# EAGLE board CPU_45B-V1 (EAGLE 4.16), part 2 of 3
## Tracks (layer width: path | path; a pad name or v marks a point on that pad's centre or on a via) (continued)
P1.7  (via drill 0.2) (continued)
  Top 0.12: U300.B10 52.15,41.23 52.15,40.59 52.23,40.51 52.23,38.43 | U430.C2 38.15,43.23 v41.91,43.23 | 52.23,38.43 52.55,38.11 52.55,36.91 52.23,36.59 49.27,36.59 v48.87,36.99 | v44.95,35.07 44.63,34.75 23.71,34.75 14.51,43.95 9.31,43.95 7.07,46.19 5.19,46.19 3.75,45.79 X200.70 | 52.23,38.43
  Route3 0.12: v48.87,36.99 48.31,37.55 | v41.91,43.23 41.91,42.95 47.31,37.55 48.31,37.55 | 48.31,37.55
  Route14 0.12: v44.95,35.07 47.43,37.55 48.31,37.55 v48.87,36.99
P1.8  (via drill 0.2)
  Top 0.12: U430.C1 41.19,43.63 41.43,43.87 v41.67,43.87 | v48.39,38.11 48.39,36.83 48.87,36.35 52.35,36.35 52.83,36.83 52.83,38.35 52.55,38.63 U300.A10 | v44.15,35.15 43.99,34.99 23.83,34.99 14.63,44.19 9.43,44.19 6.71,46.91 4.95,46.91 3.59,46.59 X200.72
  Route3 0.12: 42.07,43.87 | 42.07,43.87 v41.67,43.87 | v48.39,38.11 47.11,38.11 42.51,42.71 42.51,43.43 42.07,43.87 | 42.07,43.87 v41.67,43.87 | v41.67,43.87
  Route14 0.12: v48.39,38.11 47.11,38.11 v44.15,35.15
P1.9  (via drill 0.2)
  Top 0.12: U300.B11 51.35,41.23 51.35,40.59 51.27,40.51 51.27,39.71 51.07,39.51 v51.07,38.59 | U430.B2 37.35,42.43 v37.35,41.23 | v44.23,35.87 43.59,35.23 23.95,35.23 14.75,44.43 9.55,44.43 6.27,47.71 4.71,47.71 3.35,47.31 X200.74
  Route3 0.12: v37.35,41.23 39.07,41.23 44.23,36.07 v44.23,35.87
  Route14 0.12: v51.07,38.59 51.03,38.59 46.95,38.59 v44.23,35.87
P1.10  (via drill 0.2)
  Top 0.12: 50.15,43.23 U300.D12 | 50.15,43.23 | 50.15,43.23 49.91,43.23 v49.43,42.75
  Route3 0.12: v12.79,24.11 13.19,23.71 13.91,23.71 14.79,24.59 22.87,24.59 23.35,25.07 50.23,25.07 v50.71,25.55
  Route14 0.12: v49.43,42.75 49.43,41.63 51.99,39.07 51.99,37.87 50.47,36.35 50.47,25.79 v50.71,25.55
  Bottom 0.12: X200.19 11.19,23.63 12.31,23.63 v12.79,24.11
P1.11  (via drill 0.2)
  Top 0.12: U300.D11 51.35,43.63 49.59,43.63 v48.71,42.75
  Route3 0.12: v13.59,24.11 14.31,24.83 22.71,24.83 23.19,25.31 49.03,25.31 49.27,25.55 v49.99,25.55
  Route14 0.12: v48.71,42.75 48.71,41.99 51.75,38.95 51.75,38.03 50.23,36.51 50.23,25.79 v49.99,25.55
  Bottom 0.12: X200.17 11.35,22.99 11.67,23.31 12.79,23.31 v13.59,24.11
P1.12  (via drill 0.2)
  Top 0.12: v34.15,48.03 U430.H7 | U300.E11 51.35,44.43 v49.59,44.43
  Route3 0.12: v49.59,44.43 42.87,44.43 40.95,46.35 37.95,46.35 37.39,45.79 36.19,45.79 34.87,47.11 34.87,47.71 34.55,48.03 | v34.15,48.03 34.55,48.03 | 34.55,48.03
P1.13  (via drill 0.2)
  Top 0.12: v32.55,48.03 U430.H8 | v49.11,44.03 U300.E12 | v49.11,44.03
  Route3 0.12: v49.11,44.03 42.87,44.03 40.79,46.11 38.07,46.11 37.51,45.55 34.31,45.55 33.35,46.51 33.35,47.23 v32.55,48.03
P1.14  (via drill 0.2)
  Top 0.12: v32.55,48.83 U430.J8
  Top 0.127: v52.15,43.63 U300.E10
  Route3 0.12: v52.15,43.63 42.87,43.63 40.63,45.87 38.19,45.87 37.63,45.31 32.95,45.31 32.15,46.11 32.15,48.43 v32.55,48.83 | v32.55,48.83
P1.15  (via drill 0.2)
  Top 0.12: U430.J7 v34.15,48.83 | U300.G12 v49.11,45.63
  Route3 0.12: v49.11,45.63 48.71,45.23 42.47,45.23 41.11,46.59 37.83,46.59 37.27,46.03 36.31,46.03 35.11,47.23 35.11,47.87 v34.15,48.83
P2.0  (via drill 0.2)
  Top 0.12: v36.55,48.83 U430.J3 | U300.J11 51.35,47.63 49.59,47.63 v49.11,47.15
  Route3 0.12: v49.11,47.15 48.55,47.15 48.23,46.83 36.31,46.83 36.15,46.99 36.15,48.43 v36.55,48.83 | v36.55,48.83
P2.1  (via drill 0.2)
  Top 0.12: U430.J2 38.23,48.91 40.07,48.91 v40.95,48.03 | v40.95,48.03 | v50.39,48.03 U300.K12 | U500.2 36.51,70.46 36.3,70.46 v35.98,70.77 | R404.2 34.79,28.19 35.43,28.19 v37.67,30.43 | U500.24 46.45,70.19 v46.95,70.19
  Route3 0.12: v40.95,48.03 | v40.95,48.03 v50.39,48.03 | v35.98,70.77 40.29,70.77 43.11,67.95 45.91,67.95 46.95,68.99 v46.95,70.19
  Route14 0.12: v37.67,30.43 38.71,31.47 38.71,43.79 40.95,46.03 v40.95,48.03 41.11,48.19 41.11,60.75 43.75,63.39 43.75,63.95 44.63,64.83 46.07,64.83 47.19,65.95 47.19,69.95 v46.95,70.19
P2.2  (via drill 0.2)
  Top 0.12: U430.H3 v36.55,48.03 | U300.K11 51.35,48.43 50.15,48.43 49.75,48.03 49.19,48.03 v48.79,47.63
  Route3 0.12: v36.55,48.03 | v48.79,47.63 U430.H3 v36.55,48.03
P2.3  (via drill 0.2)
  Top 0.12: U430.H2 v38.15,48.03 | 51.35,49.23 U300.L11 | v49.03,48.99 49.35,49.31 50.23,49.31 50.31,49.23 51.35,49.23 | 51.35,49.23
  Route3 0.12: v38.15,48.03 38.79,48.67 48.71,48.67 v49.03,48.99
P2.4  (via drill 0.2)
  Top 0.12: U430.H1 v38.95,48.03 | U300.L10 52.15,49.23 52.15,52.19 48.95,55.39 39.43,55.39 v38.95,54.91
  Route14 0.12: v38.95,48.03 v38.95,54.91
P2.5  (via drill 0.2)
  Top 0.12: U430.G3 v36.55,47.23 | U300.M10 52.55,52.15 49.07,55.63 39.03,55.63 38.31,54.91 37.59,54.19 v36.95,54.19
  Route14 0.12: v36.95,54.19 36.95,47.63 v36.55,47.23
P2.6  (via drill 0.2)
  Top 0.12: v11.99,28.27 11.03,28.27 10.47,27.71 8.71,27.23 X200.30
  Top 0.127: v52.95,47.63 U300.J9
  Route3 0.12: v52.95,47.63 52.55,48.03 52.55,48.67 50.39,50.83 33.11,50.83 31.11,48.83 v31.11,47.63 | v11.99,28.27 12.71,27.55 v31.11,27.55
  Route14 0.12: v31.11,27.55 v31.11,47.63
P2.7  (via drill 0.2)
  Top 0.12: v12.07,27.31 10.79,27.31 10.39,26.91 8.87,26.43 X200.28
  Top 0.127: v52.95,48.43 U300.K9
  Route3 0.12: v52.95,48.43 52.95,48.67 50.55,51.07 32.99,51.07 30.63,48.71 v30.63,48.03 | v30.63,27.15 24.95,27.15 24.79,27.31 v12.07,27.31
  Route14 0.12: v30.63,48.03 30.63,47.47 30.87,47.23 30.87,29.15 30.63,28.91 v30.63,27.15
P2.8  (via drill 0.2)
  Top 0.12: U430.H9 v31.75,48.03 | U300.L9 52.95,49.23 52.95,52.11 49.19,55.87 38.87,55.87 37.83,54.83 34.71,54.83 33.51,56.03 v32.15,56.03 | v32.15,56.03 | v32.15,56.03
  Route14 0.12: v31.75,48.03 32.15,48.43 v32.15,56.03
P2.9  (via drill 0.2)
  Top 0.12: U430.G2 v38.15,47.23 | U300.M9 53.35,52.07 49.31,56.11 38.79,56.11 38.47,56.11 v37.75,55.39 | v37.75,55.39 | v37.75,55.39
  Route14 0.12: v38.15,47.23 | v37.75,55.39 37.75,47.63 v38.15,47.23
P2.10  (via drill 0.2)
  Top 0.12: U430.G7 v34.15,47.23 | U300.L8 53.75,49.23 53.75,52.03 49.43,56.35 37.99,56.35 36.71,55.07 35.11,55.07 v34.15,56.03 | v34.15,56.03 | v34.15,56.03
  Route14 0.12: v34.15,47.23 33.75,47.63 33.75,55.63 v34.15,56.03
P2.11  (via drill 0.2)
  Top 0.12: U430.G8 v32.55,47.23 | U300.M8 54.15,51.99 49.55,56.59 37.87,56.59 36.59,55.31 35.91,55.31 34.71,56.51 v32.95,56.51
  Route14 0.12: v32.55,47.23 32.95,47.63 v32.95,56.51
P2.12  (via drill 0.2)
  Top 0.12: U300.L7 54.55,49.23 54.55,53.31 v53.91,53.95 | X200.16 11.51,22.35 v12.71,22.35
  Route3 0.12: v53.91,53.95 50.87,53.95 49.19,52.27 32.31,52.27 29.27,49.23 29.27,47.15 30.31,46.11 30.31,44.63 29.59,43.91 29.59,39.63 | v29.11,38.91 29.11,39.15 29.59,39.63 | 29.59,39.63
  Route14 0.12: v29.11,38.91 29.11,33.23 19.67,23.79 16.75,23.79 15.07,22.11 13.75,22.11 13.59,21.95 13.11,21.95 v12.71,22.35
P2.13  (via drill 0.2)
  Top 0.12: U300.M7 54.95,53.55 54.15,54.35 v53.43,54.35 | X200.14 11.83,21.55 12.55,21.55 v13.35,22.35
  Route3 0.12: v53.43,54.35 53.27,54.19 50.71,54.19 49.03,52.51 32.19,52.51 29.03,49.35 29.03,47.03 30.07,45.99 30.07,44.75 29.35,44.03 29.35,39.79 28.71,39.15 v28.71,38.43
  Route14 0.12: v28.71,38.43 28.71,33.19 19.55,24.03 16.63,24.03 14.95,22.35 v13.35,22.35
P2.14  (via drill 0.2)
  Top 0.12: v32.55,44.83 U430.E8
  Top 0.127: v54.55,48.43 U300.K7
  Route3 0.12: v54.55,48.43 54.15,48.03 53.51,48.03 53.35,48.19 53.35,48.67 50.71,51.31 32.79,51.31 30.23,48.75 30.23,47.63 31.27,46.59 31.27,46.11 v32.55,44.83 | v32.55,44.83 | v32.55,44.83 | v32.55,44.83
  Bottom 0.12: X200.55 6.63,40.75 7.75,40.75 10.55,43.55 28.87,43.55 30.63,45.31 32.07,45.31 v32.55,44.83 | v32.55,44.83 | v32.55,44.83
P2.15  (via drill 0.2)
  Top 0.12: U430.F1 41.67,46.03 v42.31,46.03 | v42.31,46.03
  Top 0.127: v56.15,47.63 U300.J6
  Route3 0.12: v56.15,47.63 | v42.31,46.03 | v42.31,46.03 42.71,46.43 54.95,46.43 v56.15,47.63
  Bottom 0.12: v42.31,46.03 | v42.31,46.03 35.27,46.03 33.67,44.43 30.15,44.43 29.03,43.31 10.71,43.31 7.43,40.03 6.79,40.03 X200.53
P3.0  (via drill 0.2)
  Top 0.12: U300.C1 60.15,42.43 63.35,39.23 v63.83,39.23
  Bottom 0.12: 63.75,39.15 v63.83,39.23 63.51,38.91 55.83,38.91 55.51,39.23 51.07,39.23 47.47,42.83 10.63,42.83 7.03,39.23 X200.51
P3.1  (via drill 0.2)
  Top 0.12: v31.75,46.43 U430.F9 | U300.B2 59.35,41.23 59.99,41.23 60.23,40.99 60.23,39.71 61.03,38.91 61.03,38.03 60.47,37.47 v58.47,37.47 | v31.51,42.43 31.35,42.27 31.35,37.55 31.51,37.39 v31.67,37.39
  Route14 0.12: v31.75,46.43 31.35,46.03 31.35,42.59 v31.51,42.43
  Bottom 0.12: v58.47,37.47 58.31,37.63 42.79,37.63 42.55,37.87 41.99,37.87 41.51,37.39 v31.67,37.39 | X200.49 5.83,38.03 7.27,38.59 7.59,39.39 10.63,42.43 v31.51,42.43
P3.2  (via drill 0.2)
  Top 0.12: v31.75,47.23 U430.G9 | U300.B3 58.55,41.23 58.55,40.27 57.91,39.63 57.91,37.39 v58.47,36.83 | v31.75,47.23 | v28.31,37.07 27.35,38.03 27.35,38.83 29.75,41.23 31.03,42.51 31.03,46.11 31.03,46.51 | v31.75,47.23 | v31.75,47.23 | v31.75,47.23 31.51,46.99 31.03,46.51 | 31.03,46.51 | R431.1 30.58,46.96 31.03,46.51
  Bottom 0.12: v28.31,37.07 28.39,36.99 42.39,36.99 42.79,37.39 57.91,37.39 v58.47,36.83
P3.3  (via drill 0.2)
  Top 0.12: U302.1 24.87,25.87 24.23,26.51 v24.23,26.91 | U302.1 26.07,25.47 | U302.1 25.83,25.55 R309.1 27.67,25.07 SJ1.1
  Top 0.127: v54.55,44.43 U300.F7
  Route3 0.12: v54.95,28.03 54.71,28.27 32.55,28.27 31.03,26.75 24.79,26.75 24.63,26.91 v24.23,26.91
  Route14 0.12: v54.55,44.43 54.95,44.03 v54.95,28.03
P3.4  (via drill 0.2)
  Top 0.12: v54.55,43.63 U300.E7 | v54.55,43.63
  Route3 0.12: v54.55,43.63 54.79,43.63 55.35,43.07 55.35,39.15 55.03,38.83 55.03,30.27 v54.55,29.79 | v60.87,29.79 61.19,29.47 63.99,29.47 64.31,29.79 68.71,29.79 69.03,30.11 70.79,30.11 70.95,30.27 72.07,30.27 72.39,29.95 v72.39,29.63
  Bottom 0.12: v54.55,29.79 54.71,29.63 59.99,29.63 60.15,29.79 v60.87,29.79 | v72.39,29.63 72.39,28.67 77.51,23.55 78.55,23.55 79.75,22.35 | X202.25 81.11,20.03 79.75,21.39 79.75,21.87 79.75,22.35 | 79.75,22.35
P3.5  (via drill 0.2)
  Top 0.12: v33.35,43.23 U430.C8 | U300.B6 56.15,41.23 56.15,40.43 56.31,40.27 56.31,37.75 56.15,37.59 | 56.15,37.59 52.27,33.71 v49.27,33.71 | v49.27,33.71 | v49.27,33.71 48.19,33.71 47.55,33.07 22.87,33.07 13.67,42.27 8.79,42.27 7.59,41.07 5.19,40.35 X200.56 | 56.15,37.59
  Route3 0.12: 39.03,43.23 v33.35,43.23 | v49.27,33.71 | v49.27,33.71 48.55,33.71 39.03,43.23 | 39.03,43.23
P3.6  (via drill 0.2)
  Top 0.12: v32.55,44.03 U430.D9 | 54.95,37.31 U300.A7 | v48.79,34.11 52.31,34.11 54.95,36.75 54.95,37.31 | 54.95,37.31 | 54.95,37.31 | v48.79,34.11 | v48.79,34.11 48.23,34.11 47.43,33.31 22.99,33.31 13.79,42.51 7.43,42.51 6.47,41.55 X200.58
  Route3 0.12: v32.55,44.03 32.95,43.63 39.07,43.63 | v48.79,34.11 | v48.79,34.11 48.59,34.11 39.07,43.63 | 39.07,43.63
P3.7  (via drill 0.2, 0.2 pad 0.55)
  Top 0.12: v76.23,22.91 76.23,21.79 77.51,20.51 77.51,19.07 78.87,17.71 X202.34 | X201.34 53.11,84.43 52.39,81.47 51.35,80.43 v51.35,80.11
  Top 0.127: v57.75,43.63 U300.E4
  Route3 0.12: v57.75,43.63 58.15,43.23 v74.07,43.23 | v51.67,68.43 51.83,68.27 57.91,68.27 58.47,68.83 70.39,68.83 v70.71,69.15
  Route14 0.12: v70.71,69.15 70.71,68.67 73.83,65.55 73.83,45.71 74.07,45.47 v74.07,43.23 75.03,42.27 75.03,35.55 77.11,33.47 77.11,23.79 v76.23,22.91
  Bottom 0.12: v51.67,68.43 51.43,68.67 51.43,71.63 51.19,71.87 51.19,79.55 51.35,79.71 v51.35,80.11
P3.8  (via drill 0.2, 0.2 pad 0.55)
  Top 0.12: v76.87,22.27 76.87,21.55 77.83,20.59 77.83,19.87 79.35,18.35 79.35,18.33 X202.32 | v50.47,79.95 51.99,81.47 51.99,83.23 52.39,84.59 X201.32
  Top 0.127: v58.55,43.63 U300.E3
  Route3 0.12: v58.55,43.63 73.59,43.63 74.87,44.91 v75.03,44.91 | v51.11,68.19 51.27,68.03 58.07,68.03 58.63,68.59 70.87,68.59 71.27,68.99 v71.27,69.55
  Route14 0.12: v71.27,69.55 71.27,68.51 74.07,65.71 74.07,45.87 v75.03,44.91 75.27,44.67 75.27,35.71 77.35,33.63 77.35,22.75 v76.87,22.27
  Bottom 0.12: v51.11,68.19 51.11,70.19 50.47,70.83 v50.47,79.95
P3.9  (via drill 0.2, 0.2 pad 0.55)
  Top 0.12: v75.59,23.55 75.59,22.03 77.19,20.43 77.19,18.27 78.31,17.15 78.27,17.23 X202.36 | X201.36 53.91,84.19 53.27,81.95 51.91,80.59 v51.91,79.15
  Top 0.127: v56.95,44.43 U300.F5
  Route3 0.12: v56.95,44.43 57.35,44.83 v73.19,44.83 | 69.19,69.31 53.11,69.31 v52.71,68.91 | 69.19,69.31 | v69.43,69.55 69.19,69.31
  Route14 0.12: 73.59,65.39 73.59,45.23 v73.19,44.83 73.59,44.43 73.59,42.99 74.79,41.79 74.79,35.39 76.87,33.31 76.87,24.83 v75.59,23.55 | 73.59,65.39 | 73.59,65.39 v69.43,69.55
  Bottom 0.12: v51.91,79.15 51.91,71.95 52.39,71.47 52.39,69.23 v52.71,68.91
P3.10  (via drill 0.2)
  Top 0.12: v54.07,68.75 | v54.07,68.75 | SJ3.1 53.27,69.56 v54.07,68.75 | SJ4.1 77.83,25.16 v77.83,25.31
  Top 0.127: v56.15,44.43 U300.F6
  Route3 0.12: 56.79,45.07 v56.15,44.43 | 56.79,45.07 | 56.79,45.07 72.71,45.07 73.27,45.63 v75.27,45.63 | v54.07,68.75 54.39,69.07 54.79,69.07 69.67,69.07 v70.15,69.55
  Route14 0.12: 70.71,70.11 v70.15,69.55 | 70.71,70.11 | 70.71,70.11 71.43,70.11 74.31,67.23 74.31,46.59 v75.27,45.63 75.51,45.39 75.51,35.87 77.59,33.79 77.59,25.87 77.59,25.55 v77.83,25.31
P3.12  (via drill 0.2, 0.2 pad 0.55)
  Top 0.12: U300.D3 U300.D2 59.35,42.83 60.15,42.83 63.35,39.63 65.83,39.63 v67.75,37.71 | v76.71,19.95 76.71,20.43 70.31,26.83 v70.31,28.35 70.31,29.07 69.99,29.39 69.99,35.47 v67.75,37.71 | v67.75,37.71 | v67.75,37.71 | R306.1 68.5,38.46 v67.75,37.71
  Route3 0.12: v70.31,28.35 69.43,28.35 69.19,28.59 65.11,28.59 63.27,26.75 54.39,26.75 53.83,27.31 33.11,27.31 31.59,25.79 23.35,25.79 22.79,26.35 17.23,26.35 16.19,25.31 14.99,25.31 13.63,26.67 11.71,26.67 10.23,28.15 v10.23,30.03 | v69.43,60.91 v53.11,60.91
  Route14 0.12: v67.75,37.71 68.87,38.83 68.87,44.51 70.15,45.79 70.15,48.83 69.19,49.79 69.19,60.67 v69.43,60.91 | v69.43,60.91 | v69.43,60.91
  Bottom 0.12: v76.71,19.95 76.71,19.47 76.47,19.23 76.47,17.79 77.67,16.59 77.7,16.59 X202.37 | v53.11,60.91 53.11,69.23 52.63,69.71 52.63,71.63 52.39,71.87 52.39,80.67 54.23,82.51 54.63,83.95 X201.37 | X200.37 9.27,30.67 9.59,30.67 v10.23,30.03
P3.13  (via drill 0.2)
  Top 0.12: U300.C2 59.35,42.03 60.15,42.03 63.35,38.83 65.99,38.83 v67.75,37.07 69.75,35.07 v69.75,28.83 69.75,26.99 76.23,20.51 76.23,19.47 76.47,19.23 76.47,17.79 77.67,16.59 77.7,16.59 X202.38 | v10.63,30.51 9.35,30.51 7.83,30.35 X200.38 | X201.38 54.63,83.95 54.55,83.47 54.47,83.39 54.23,82.51 52.39,80.67 52.39,78.91 v52.87,78.43 | R307.1 69.67,39.66 v69.67,38.59
  Route3 0.12: v69.75,28.83 64.95,28.83 63.11,26.99 54.55,26.99 53.99,27.55 32.95,27.55 31.43,26.03 23.51,26.03 22.95,26.59 17.11,26.59 16.07,25.55 15.11,25.55 13.75,26.91 11.83,26.91 10.63,28.11 v10.63,30.51 | v69.99,60.51 68.87,60.51 68.71,60.67 53.83,60.67 v53.59,60.43
  Route14 0.12: v69.99,60.51 | v69.99,60.51 | v69.99,60.51 69.43,59.95 69.43,49.95 70.39,48.99 70.39,45.63 69.11,44.35 | 69.11,44.35 | 69.11,44.35 69.11,39.15 v69.67,38.59 68.15,37.07 v67.75,37.07
  Bottom 0.12: v52.87,78.43 52.87,69.87 53.35,69.39 53.35,61.39 53.59,61.15 v53.59,60.43
P3.14  (via drill 0.2)
  Top 0.12: v56.15,42.83 | v56.15,42.83 U300.D6 | 78.55,21.79 71.43,28.91 v71.43,29.63 | X200.6 11.19,17.95 12.87,18.43 14.47,20.03 14.47,20.59 16.71,22.83 18.39,24.51 21.11,24.51 24.07,27.47 25.03,27.47 25.27,27.23 U302.2 27.35,26.59 29.51,26.59 29.91,26.99 29.91,27.39 30.63,28.11 v31.67,28.11 | X202.28 80.47,19.46 80.47,19.47 79.03,20.91 78.55,21.39 78.55,21.79 | 78.55,21.79
  Route3 0.12: v55.91,28.99 55.43,28.51 32.07,28.51 v31.67,28.11 | v59.43,28.99 64.31,28.99 64.63,29.31 69.03,29.31 69.35,29.63 v71.43,29.63
  Route14 0.12: v56.15,42.83 56.55,42.43 56.55,29.63 56.31,29.39 | v55.91,28.99 56.31,29.39 | 56.31,29.39
  Bottom 0.12: v55.91,28.99 v59.43,28.99
P3.15  (via drill 0.2)
  Top 0.12: v15.43,20.91 15.43,20.27 12.79,17.63 11.35,17.23 X200.4 | X202.26 81.11,20.03 79.75,21.39 79.59,21.55 v79.27,21.55 | v15.43,25.95 v15.43,29.39 17.51,31.47 18.79,31.47 U302.5
  Top 0.127: v54.55,42.83 U300.D7
  Route3 0.12: v54.55,42.83 54.15,42.43 54.15,41.67 53.95,41.47 53.95,34.07 49.27,29.39 v48.55,29.39 48.39,29.23 23.11,29.23 22.95,29.39 v15.43,29.39 | v71.99,29.15 71.99,29.71 71.67,30.03 71.11,30.03 70.95,29.87 69.19,29.87 68.87,29.55 64.47,29.55 64.15,29.23 60.55,29.23 v60.39,29.39
  Bottom 0.12: v48.55,29.39 v60.39,29.39 | v15.43,20.91 15.43,22.83 15.83,23.23 15.83,24.35 15.43,24.75 v15.43,25.95 | v79.27,21.55 79.27,22.43 78.39,23.31 77.35,23.31 71.99,28.67 v71.99,29.15
P4.0  (via drill 0.2)
  Top 0.12: v39.35,45.23 U430.E1 | U300.B8 53.75,41.23 53.75,36.63 52.43,35.31 v49.27,35.31 | v49.27,35.31 | v49.27,35.31 48.35,35.31 47.07,34.03 23.35,34.03 14.15,43.23 8.91,43.23 8.03,44.11 6.55,44.11 5.75,43.87 4.31,43.47 X200.64
  Route3 0.12: v39.35,45.23 39.35,44.43 48.47,35.31 v49.27,35.31 | v49.27,35.31
P4.1  (via drill 0.2)
  Top 0.12: v40.71,44.03 38.15,44.03 U430.D2 | U300.A9 53.35,36.59 52.47,35.71 v48.79,35.71 | v48.79,35.71 | v48.79,35.71 48.39,35.71 46.95,34.27 23.47,34.27 14.27,43.47 9.03,43.47 7.91,44.59 5.59,44.59 4.15,44.27 X200.66
  Route3 0.12: 40.71,43.43 v40.71,44.03 | v48.79,35.71 48.43,35.71 40.71,43.43 | 40.71,43.43
P4.2  (via drill 0.2)
  Top 0.12: v53.75,43.63 U300.E8
  Route3 0.12: v53.75,43.63 | v53.75,43.63 54.15,43.23 54.79,43.23 55.07,42.95 55.07,41.83 54.79,41.55 54.79,30.67 v54.55,30.43 | v60.39,30.19 61.19,30.19 61.67,29.71 63.83,29.71 64.15,30.03 68.55,30.03 68.87,30.35 70.63,30.35 70.79,30.51 72.31,30.51 72.79,30.03 v72.79,29.15
  Bottom 0.12: v54.55,30.43 55.11,29.87 59.75,29.87 60.07,30.19 v60.39,30.19 | X202.23 80.07,22.18 80.07,22.43 78.71,23.79 77.75,23.79 77.59,23.95 72.79,28.75 v72.79,29.15
P4.3  (via drill 0.2)
  Top 0.12: v71.99,71.39 71.99,76.43 72.63,77.07 73.19,79.07 X201.78
  Top 0.127: v53.75,44.43 U300.F8
  Route3 0.12: v53.75,44.43 53.35,44.03 53.35,41.67 53.15,41.47 53.15,33.91 v49.11,29.87
  Route14 0.12: v78.31,30.35 78.31,33.87 75.99,36.19 75.99,47.47 74.55,48.91 74.55,67.39 71.99,69.95 v71.99,71.39
  Bottom 0.12: v78.31,30.35 73.51,30.35 73.11,30.75 69.67,30.75 68.63,29.71 62.87,29.71 61.27,31.31 59.59,31.31 59.11,30.83 56.95,30.83 56.07,30.83 55.35,31.55 53.35,31.55 51.67,29.87 v49.11,29.87
P4.4  (via drill 0.2)
  Top 0.12: v54.55,42.03 | v54.55,42.03 U300.C7 | X201.76 72.39,79.23 71.99,77.79 71.99,76.83 71.67,76.51 71.67,72.99 v71.59,72.91
  Route3 0.12: v54.55,42.03 54.55,31.15 53.75,30.35 v53.75,29.79
  Route14 0.12: v71.59,72.91 72.47,72.91 73.27,72.11 73.27,69.87 75.27,67.87 75.27,49.39 76.71,47.95 76.71,36.67 79.19,34.19 79.19,29.31 v78.31,28.43
  Bottom 0.12: v53.75,29.79 53.75,30.35 54.23,30.83 54.87,30.83 55.59,30.11 59.59,30.11 60.07,30.59 60.79,30.59 62.39,28.99 69.11,28.99 70.15,30.03 72.63,30.03 73.03,29.63 77.11,29.63 v78.31,28.43
P4.5  (via drill 0.2)
  Top 0.12: v53.75,42.83 | v53.75,42.83 U300.D8
  Route14 0.12: v53.75,42.83 53.35,42.43 53.35,31.15 52.95,30.75 v52.95,29.79 | v78.31,29.71 78.71,30.11 78.71,33.87 76.23,36.35 76.23,47.63 74.79,49.07 74.79,67.55 72.45,69.9 v72.45,71.89
  Bottom 0.12: v52.95,29.79 52.95,30.75 53.51,31.31 | v78.31,29.71 77.91,30.11 73.35,30.11 72.95,30.51 69.83,30.51 68.79,29.47 62.71,29.47 61.11,31.07 59.75,31.07 59.27,30.59 55.91,30.59 55.19,31.31 53.51,31.31 | v72.45,71.89 71.99,72.35 71.99,76.43 72.63,77.07 73.19,79.07 X201.77 | 53.51,31.31
P4.6  (via drill 0.2)
  Top 0.12: v53.75,42.03 | v53.75,42.03 | v53.75,42.03 U300.C8
  Route14 0.12: v53.75,42.03 53.75,30.99 53.35,30.59 v53.35,30.43 | v71.27,72.27 71.43,72.43 72.55,72.43 73.03,71.95 73.03,69.71 75.03,67.71 75.03,49.23 76.47,47.79 76.47,36.51 78.95,34.03 78.95,29.71 v78.31,29.07
  Bottom 0.12: v53.35,30.43 53.35,30.59 53.83,31.07 55.03,31.07 55.75,30.35 59.43,30.35 59.91,30.83 60.95,30.83 62.55,29.23 68.95,29.23 69.99,30.27 72.79,30.27 73.19,29.87 77.51,29.87 v78.31,29.07 | X201.75 72.39,79.23 71.99,77.79 71.99,76.83 71.67,76.51 71.67,73.79 71.11,73.23 71.11,72.43 v71.27,72.27
P4.7  (via drill 0.2)
  Top 0.12: v52.95,42.03 | v52.95,42.03 U300.C9 | v39.59,30.51 39.75,30.35 48.55,30.35 48.87,30.67 51.51,30.67 v51.67,30.51
  Route3 0.12: v47.99,66.27 v53.91,66.27
  Route14 0.12: v52.95,42.03 52.95,37.63 51.35,36.03 51.35,30.83 v51.67,30.51 | v39.59,30.51 39.19,30.91 39.19,43.47 41.59,45.87 41.59,60.35 44.23,62.99 44.23,63.63 44.95,64.35 46.39,64.35 47.99,65.95 v47.99,66.27 | v47.99,66.27
  Bottom 0.12: X201.41 56.23,83.55 55.75,82.19 53.75,80.19 53.59,80.03 53.59,78.83 53.59,71.47 53.83,71.23 53.83,70.27 53.59,70.03 53.59,66.59 v53.91,66.27
P5.0  (via drill 0.2)
  Top 0.127: v52.95,46.83 U300.H9
  Route3 0.12: v50.31,52.75 49.43,52.03 32.43,52.03 29.51,49.11 29.51,47.27 30.55,46.23 30.55,44.51 29.83,43.79 | v29.51,38.43 29.51,39.15 29.83,39.47 29.83,43.79 | 29.83,43.79
  Route14 0.12: v52.95,46.83 52.55,47.23 52.55,48.87 50.31,51.11 v50.31,52.75 | v29.51,38.43 29.51,33.27 19.79,23.55 16.87,23.55 15.19,21.87 13.91,21.87 13.59,21.55 v13.35,21.55
  Bottom 0.12: 9.43,21.63 10.71,21.95 10.07,21.87 X200.15 11.59,22.03 12.31,22.03 12.79,21.55 v13.35,21.55
P5.1  (via drill 0.2)
  Top 0.127: v53.75,46.83 U300.H8
  Route3 0.12: v50.71,52.03 50.47,51.79 32.55,51.79 29.75,48.99 29.75,47.39 30.79,46.35 30.79,44.39 30.07,43.67 30.07,40.67 | v29.91,38.91 30.07,39.07 30.07,40.67 | 30.07,40.67
  Route14 0.12: v53.75,46.83 53.35,47.23 53.35,48.67 53.03,48.99 52.79,48.99 50.71,51.07 v50.71,52.03 | v12.47,21.15 13.55,21.15 14.03,21.63 15.31,21.63 16.99,23.31 19.91,23.31 29.91,33.31 v29.91,38.91
  Bottom 0.12: 10.39,21.07 9.67,20.83 | v12.47,21.15 12.31,21.31 11.75,21.31 X200.13 10.39,21.07 | 10.39,21.07 10.87,21.23
P5.2  (via drill 0.2)
  Top 0.12: v54.55,46.83 | v54.55,46.83 U300.H7 | v54.55,46.83 | V300.C 26.42,50.3 v29.43,53.31
  Route14 0.12: v54.55,46.83 55.75,45.63 55.75,38.91 55.51,38.67 55.51,38.19 55.67,38.03 v55.67,31.87 | v24.79,37.55 27.27,40.03 29.51,40.03 30.15,40.67 30.15,46.75 29.67,47.23 29.67,53.07 v29.43,53.31
  Bottom 0.12: v55.67,31.87 51.91,31.87 50.39,30.35 41.91,30.35 36.39,35.87 25.83,35.87 24.79,36.91 v24.79,37.55
P5.3  (via drill 0.2)
  Top 0.12: U430.F3 v36.55,46.43
  Top 0.127: v52.15,47.63 U300.J10
  Route3 0.12: v52.15,47.63 50.39,49.39 36.47,49.39 35.91,48.83 35.91,46.87 36.35,46.43 v36.55,46.43
P5.4  (via drill 0.2)
  Top 0.12: U430.F8 v32.55,46.43
  Top 0.127: v52.15,48.43 U300.K10
  Route3 0.12: v52.15,48.43 50.15,50.43 v33.35,50.43
  Route14 0.12: v32.55,46.43 33.35,47.23 v33.35,50.43
P5.5  (via drill 0.2)
  Top 0.12: U430.F7 v34.15,46.43
  Top 0.127: v53.75,47.63 U300.J8
  Route3 0.12: v53.75,47.63 53.35,47.23 51.75,47.23 50.55,48.43 40.71,48.43 v40.31,48.03
  Bottom 0.12: v34.15,46.43 35.35,47.63 39.91,47.63 v40.31,48.03
P5.6  (via drill 0.2)
  Top 0.12: SJ5.1 73.77,21.14 v73.19,21.71 | v50.95,71.15 53.51,71.15 53.83,71.47 53.83,71.43 SJ2.1
  Top 0.127: v53.75,48.43 U300.K8
  Route3 0.12: v73.75,71.71 72.15,73.31 63.51,73.31 61.35,71.15 v50.95,71.15 | v50.95,71.15
  Route14 0.12: v53.75,48.43 53.75,52.75 52.47,54.03 52.47,59.15 52.07,59.55 52.07,66.51 50.71,67.87 50.71,70.91 v50.95,71.15 | v50.95,71.15 | v50.95,71.15 | v73.19,21.71 74.15,20.75 78.07,20.75 78.55,21.23 78.55,27.95 79.43,28.83 79.43,30.35 79.43,34.35 76.95,36.83 76.95,48.11 75.51,49.55 75.51,68.03 73.75,69.79 v73.75,71.71
P5.7  (via drill 0.2, 0.2 pad 0.55)
  Top 0.12: v54.55,47.63 | v54.55,47.63 U300.J7
  Route3 0.12: v72.15,50.99 71.35,51.79 70.39,51.79 70.07,51.47 60.39,51.47 59.67,52.19 56.55,52.19 v56.23,52.51
  Route14 0.12: v54.55,47.63 54.95,48.03 54.95,51.23 v56.23,52.51 | v74.47,23.47 74.47,29.31 71.75,32.03 71.75,50.59 v72.15,50.99
  Bottom 0.12: X202.41 76.57,15.55 76.55,15.55 75.59,16.51 75.59,17.71 74.23,19.07 74.23,23.23 v74.47,23.47 | v74.47,23.47 | v74.47,23.47
P5.8  (via drill 0.2)
  Top 0.12: U430.F2 38.15,45.63 38.15,45.07 38.39,44.83 39.67,44.83 39.91,45.07 39.91,45.31 arc-90 40.23,45.63 arc-90 40.55,45.31 arc90 40.87,44.99 arc90 41.19,45.31 arc-90 41.51,45.63 arc-90 41.83,45.31 arc90 42.15,44.99 arc90 42.47,45.31 v42.79,45.63 | v42.79,45.63 | 42.79,46.75 | v42.79,45.63 42.79,46.75 | R432.2 42.55,46.99 42.79,46.75
  Top 0.127: v56.15,46.83 U300.H6
  Route3 0.12: v42.79,45.63 43.27,45.63 arc0 43.43,45.79 arc-90 43.75,46.11 arc-90 44.07,45.79 arc90 44.39,45.47 arc90 44.71,45.79 arc-90 45.03,46.11 arc-90 45.35,45.79 arc90 45.67,45.47 arc90 45.99,45.79 arc-90 46.31,46.11 arc-90 46.63,45.79 arc90 46.95,45.47 arc90 47.27,45.79 arc-90 47.59,46.11 arc-90 47.91,45.79 arc90 48.23,45.47 arc90 48.55,45.79 arc-90 48.87,46.11 49.27,46.11 arc-90 49.59,45.79 arc90 49.91,45.47 arc90 50.23,45.79 arc-90 50.55,46.11 arc-90 50.87,45.79 arc90 51.03,45.63 52.31,45.63 arc-90 52.63,45.31 arc90 52.95,44.99 arc90 53.27,45.31 arc-90 53.59,45.63 arc-90 53.91,45.31 arc90 54.23,44.99 arc90 54.55,45.31 arc-90 54.87,45.63 arc53 55.03,45.71 v56.15,46.83 | v56.15,46.83
P5.9  (via drill 0.2)
  Top 0.12: v56.15,48.43 | v56.15,48.43 U300.K6
  Route3 0.12: v56.15,48.43 53.03,51.55 32.67,51.55 29.99,48.87 29.99,47.51 31.03,46.47 31.03,44.27 30.31,43.55 | v30.47,39.31 30.31,39.47 30.31,43.55 | 30.31,43.55
  Route14 0.12: v30.47,39.31 27.79,39.31 27.27,38.79 27.27,32.83 19.19,24.75 12.95,24.75 v12.71,24.99
  Bottom 0.12: v12.71,24.99 12.31,24.59 10.95,24.59 9.51,24.19 X200.21
P5.10  (via drill 0.2)
  Top 0.12: v56.95,46.83 U300.H5 | v56.95,46.83
  Top 0.2: C416.1 R429.1 33.98,53.77 33.98,54 33.52,54.45 | 33.52,54.45 | 33.52,54.45 SW401.P 32.5,55.47 31.83,55.47 v30.71,56.59 27.03,60.27 27.03,60.91 SW401.P1
  Route14 0.12: v56.95,46.83 57.35,46.43 57.35,29.15 57.51,28.99 v57.51,28.51 | v57.51,28.51 | v19.51,34.35 21.91,34.35 23.91,36.35 23.91,37.31 26.87,40.27 29.35,40.27 29.91,40.83 29.91,46.59 29.43,47.07 29.43,52.43 28.95,52.91 28.95,54.83 v30.71,56.59
  Bottom 0.12: v57.51,28.51 57.51,27.55 56.95,26.99 52.55,26.99 52.15,27.39 37.91,27.39 31.43,33.87 19.99,33.87 v19.51,34.35
P5.11  (via drill 0.2)
  Top 0.12: v56.95,47.63 U300.J5 | v78.07,24.59 78.07,24.18 X202.24
  Route3 0.12: 74.31,47.87 65.51,47.87 64.95,48.43 60.39,48.43 59.99,48.03 57.35,48.03 v56.95,47.63 | v75.27,46.91 74.31,47.87 | 74.31,47.87
  Route14 0.12: v75.27,46.91 | v75.27,46.91 75.75,46.43 75.75,36.03 77.83,33.95 77.83,26.51 78.31,26.03 78.31,24.83 v78.07,24.59 | v78.07,24.59 | v78.07,24.59
P6.0  (via drill 0.2)
  Top 0.12: v41.99,36.59 41.83,36.43 25.03,36.43 24.63,36.83 23.79,36.83 15.23,45.39 10.55,45.39 v6.95,48.99 | R421.2 v47.51,8.43
  Top 0.127: v52.15,46.03 U300.G10
  Route3 0.12: v47.51,8.43 44.87,11.07 v41.99,11.07
  Route14 0.12: v52.15,46.03 | v52.15,46.03 | v52.15,46.03 51.75,46.43 48.63,46.43 44.71,42.51 44.71,39.31 v41.99,36.59 v41.99,11.07
  Bottom 0.12: v6.95,48.99 6.71,49.23 4.31,49.23 2.87,48.91 X200.77
P6.1  (via drill 0.2)
  Top 0.12: v42.71,36.11 42.55,35.95 24.31,35.95 15.11,45.15 10.15,45.15 v7.11,48.19 | R426.2 42.79,10.59 v42.55,9.79
  Top 0.127: v52.95,44.43 U300.F9
  Route14 0.12: v52.95,44.43 | v52.95,44.43 52.55,44.83 51.91,44.83 51.51,45.23 48.23,45.23 45.19,42.19 45.19,38.59 v42.71,36.11 42.41,35.81 42.41,11.51 42.55,11.37 v42.55,9.79
  Bottom 0.12: v7.11,48.19 6.79,48.51 4.55,48.51 3.11,48.11 X200.75
P6.2  (via drill 0.2)
  Top 0.12: v42.23,37.47 41.43,36.67 25.15,36.67 24.75,37.07 23.91,37.07 15.35,45.63 10.87,45.63 v9.11,47.39 | R425.2 43.99,10.35 v43.75,9.47
  Top 0.127: v52.15,46.83 U300.H10
  Route14 0.12: v52.15,46.83 50.87,46.83 49.67,48.03 48.55,48.03 44.47,43.95 44.47,39.71 v42.23,37.47 41.51,36.75 41.51,9.95 42.15,9.31 43.59,9.31 v43.75,9.47
  Bottom 0.12: v9.11,47.39 8.79,47.71 4.71,47.71 3.27,47.31 X200.73
P6.3  (via drill 0.2)
  Top 0.12: v52.95,46.03 U300.G9 | v24.39,36.43 24.63,36.19 42.15,36.19 v42.79,36.83 42.79,37.55 41.91,38.43 v40.07,38.43 | 6.95,30.91 8.23,31.15 7.67,31.07 | v10.07,30.99 9.59,31.47 9.03,31.47 7.67,31.07 | X202.40 77.19,16.07 77.19,16.03 75.99,17.23 75.99,20.35 69.27,27.07 v69.27,27.87 | 7.67,31.07 X200.40 | X201.40 55.43,83.71 55.27,83.23 55.19,83.15 55.03,82.27 52.87,80.11 v52.87,79.15
  Route3 0.12: v69.27,27.87 68.79,28.35 65.27,28.35 63.43,26.51 54.23,26.51 53.67,27.07 33.27,27.07 31.75,25.55 23.19,25.55 22.63,26.11 17.35,26.11 16.31,25.07 14.87,25.07 13.51,26.43 11.59,26.43 9.83,28.19 9.83,30.75 v10.07,30.99
  Route14 0.12: v52.95,46.03 52.55,45.63 51.75,45.63 51.27,46.11 48.71,46.11 44.95,42.35 44.95,38.99 v42.79,36.83 | v40.07,38.43 39.91,38.59 39.91,39.79 42.87,42.75 42.87,44.67 43.43,45.23 43.43,46.03 42.31,47.15 42.31,59.87 48.87,66.43 48.87,70.19 53.35,74.67 53.35,78.67 v52.87,79.15 | v10.07,30.99 | v10.07,30.99 | v10.07,30.99 10.79,30.99 10.95,31.15 19.11,31.15 | 19.11,31.15 v24.39,36.43 | 19.11,31.15
P6.4  (via drill 0.2)
  Top 0.12: R432.1 40.87,46.99 40.63,47.23 v38.95,47.23
  Top 0.127: v52.15,44.43 U300.F10
  Bottom 0.12: 2.87,46.43 4.03,46.71 3.51,46.59 X200.71 4.95,46.91 8.71,46.91 9.99,45.63 | v52.15,44.43 50.55,46.03 48.15,46.03 arc90 47.83,45.71 47.83,44.59 arc-90 47.51,44.27 arc-90 47.19,44.59 47.19,45.71 arc90 46.87,46.03 arc90 46.55,45.71 46.55,44.59 arc-90 46.23,44.27 arc-90 45.91,44.59 45.91,45.71 arc90 45.59,46.03 arc90 45.27,45.71 45.27,44.59 arc-90 44.95,44.27 arc-90 44.63,44.59 44.63,45.71 arc90 44.31,46.03 arc90 43.99,45.71 43.99,44.59 arc-90 43.67,44.27 arc-90 43.35,44.59 43.35,45.87 41.99,47.23 v38.95,47.23 38.55,46.83 35.19,46.83 33.99,45.63 30.55,45.63 28.71,43.79 11.83,43.79 9.99,45.63 | 9.99,45.63
P6.5  (via drill 0.2)
  Top 0.12: U300.F11 51.35,45.23 49.51,45.23 v49.11,44.83 | R424.2 45.27,9.95 v45.03,9.07 | v54.44,63.4 U303.2
  Route3 0.12: v38.95,26.03 39.51,26.59 49.19,26.59 49.35,26.43 v49.83,26.43 | v54.44,63.4 54.43,63.39 45.83,63.39 v45.43,63.79
  Route14 0.12: v49.11,44.83 48.31,44.03 48.31,42.03 51.51,38.83 51.51,38.19 49.99,36.67 49.99,26.59 v49.83,26.43 | v49.83,26.43 | v38.95,26.03 39.11,26.19 39.11,28.91 40.23,30.03 40.23,30.99 39.67,31.55 39.67,39.95 42.63,42.91 42.63,44.83 43.19,45.39 43.19,45.87 42.07,46.99 42.07,60.03 45.43,63.39 v45.43,63.79 | v49.83,26.43 49.59,26.19 49.59,13.63 v45.03,9.07
P6.6  (via drill 0.2)
  Top 0.12: v50.07,44.83 U300.F12 | R423.2 46.47,9.63 v46.23,8.75 | U304.2 56.43,66.16 56.43,64.12 v55.53,63.22
  Route3 0.12: v50.95,26.59 50.71,26.83 38.87,26.83 v38.71,26.67 | v55.53,63.22 55.22,62.91 51.99,62.91 51.75,63.15 45.11,63.15 v44.79,63.47
  Route14 0.12: v50.07,44.83 51.75,43.15 51.75,41.15 52.23,40.67 52.23,37.71 50.71,36.19 50.71,27.23 50.71,26.83 v50.95,26.59 51.19,26.35 51.19,25.31 49.83,23.95 49.83,12.35 v46.23,8.75 | v38.71,26.67 38.87,26.83 38.87,29.07 39.99,30.19 39.99,30.83 39.43,31.39 39.43,40.11 42.39,43.07 42.39,44.83 41.83,45.39 41.83,60.19 44.79,63.15 v44.79,63.47
P14.0  (via drill 0.2)
  Top 0.12: U300.L3 58.55,49.23 58.55,51.15 v58.71,51.31
  Route14 0.12: v58.71,51.31 58.15,51.87 58.15,68.75 59.19,69.79 v63.43,69.79
  Bottom 0.12: v63.43,69.79 63.43,78.19 63.99,78.91 64.71,81.23 X201.55
P14.1  (via drill 0.2)
  Top 0.12: U300.L2 59.35,49.23 60.55,49.23 v60.63,49.31 | R300.S 65.45,34.19 v59.67,34.19
  Route14 0.12: v60.63,49.31 60.63,48.91 59.75,48.03 59.75,47.07 59.27,46.59 59.27,34.59 v59.67,34.19
P14.2  (via drill 0.2)
  Top 0.12: v64.71,70.67 63.67,71.71 63.67,78.03 64.95,79.31 65.51,81.07 X201.58
  Top 0.127: U300.K3 v58.55,48.43
  Route14 0.12: v58.55,48.43 59.11,48.99 59.11,51.55 58.39,52.27 58.39,68.59 59.19,69.39 63.99,69.39 64.71,70.11 v64.71,70.67
P14.3  (via drill 0.2)
  Top 0.12: v57.75,47.63 U300.J4 | v62.71,20.19 62.71,19.23 62.15,18.67 62.15,15.31 65.91,11.55 69.19,11.55 70.07,10.67 | 69.99,10.75 70,10.75 70.07,10.67 | 70.9,9.84 X202.54 70.87,9.84 70.87,9.87 70.07,10.67
  Route3 0.12: v57.75,47.63 58.15,47.23 65.11,47.23 65.35,47.47 v68.47,47.47
  Route14 0.12: v62.71,20.19 62.71,20.75 62.07,21.39 62.07,33.39 68.15,39.47 68.15,44.99 68.31,45.15 68.31,47.31 v68.47,47.47
P14.4  (via drill 0.2)
  Top 0.12: v60.63,48.03 U300.K1 | v63.51,20.19 63.51,19.31 62.39,18.19 62.39,15.47 66.07,11.79 70.07,11.79 71.43,10.43 71.43,10.41 X202.52 | v62.95,79.63 62.95,81.07 63.03,81.15 63.11,81.71 X201.52
  Route14 0.12: v63.51,20.19 63.51,20.75 62.55,21.71 62.55,33.07 68.63,39.15 68.63,44.67 69.35,45.39 69.35,48.59 v69.03,48.91 68.71,49.23 68.71,72.03 | 68.71,72.03 62.71,78.03 62.71,79.39 v62.95,79.63 | 68.71,72.03
  Bottom 0.12: v60.63,48.03 61.27,47.39 64.95,47.39 65.03,47.47 65.19,47.63 67.19,47.63 68.47,48.91 v69.03,48.91
P14.5  (via drill 0.2)
  Top 0.12: U300.K2 59.35,48.43 61.11,48.43 v61.75,47.79 | X201.8 43.11,87.07 42.79,85.63 42.79,84.67 43.43,84.03 44.71,84.03 49.03,79.71 v49.67,79.71
  Route3 0.12: v50.23,67.07 50.47,67.31 60.15,67.31 60.31,67.15 v61.75,67.15
  Route14 0.12: v61.75,47.79 v61.75,67.15
  Bottom 0.12: v50.23,67.07 50.71,67.55 50.71,70.19 50.23,70.67 50.23,79.15 v49.67,79.71
P14.6  (via drill 0.2)
  Top 0.12: 49.03,79.31 44.55,83.79 43.27,83.79 41.99,85.07 41.99,85.87 42.31,87.31 X201.6 | 49.03,79.31 | 49.03,79.31 v49.11,79.23 49.03,79.31 | 49.03,79.31 v49.11,79.23 | 49.03,79.31
  Top 0.127: U300.J3 v58.55,47.63
  Route3 0.12: v50.23,68.03 50.47,67.79 58.55,67.79 v58.87,68.11
  Route14 0.12: 59.75,48.83 59.75,52.51 58.87,53.39 v58.87,68.11 | v58.55,47.63 | 59.75,48.83 | v58.55,47.63 59.75,48.83
  Bottom 0.12: v49.11,79.23 49.11,73.71 48.07,72.67 48.07,70.19 v50.23,68.03
P14.7  (via drill 0.2)
  Top 0.12: U300.J2 v59.35,47.63 | X201.4 41.51,87.47 41.19,86.11 41.19,85.47 43.11,83.55 44.39,83.55 48.23,79.71 v48.23,79.39 | v48.23,79.39
  Route3 0.12: v60.63,67.55 v49.67,67.55
  Route14 0.12: v60.63,67.55 60.63,52.03 59.99,51.39 59.99,48.67 59.35,48.03 | 59.35,48.03 | v59.35,47.63 59.35,48.03
  Bottom 0.12: v49.67,67.55 47.83,69.39 47.83,72.83 48.87,73.87 48.87,78.75 v48.23,79.39
P14.8  (via drill 0.2)
  Top 0.12: U300.M5 56.55,51.23 v56.95,51.63 | v63.03,71.15 63.03,75.23 62.71,75.55 62.71,79.15 61.91,80.19 62.39,81.87 X201.50 | v66.31,17.15 66.47,16.99 66.47,14.67 69.11,12.03 70.95,12.03 71.99,10.99 X202.50
  Route3 0.12: v56.95,51.63 57.27,51.95 59.51,51.95 60.23,51.23 70.79,51.23 v70.95,51.39
  Route14 0.12: v56.95,51.63 57.19,51.87 57.19,69.39 58.55,70.75 61.99,70.75 62.39,71.15 v63.03,71.15 | v66.31,17.15 73.99,24.83 73.99,28.99 71.27,31.71 71.27,50.51 70.95,50.83 v70.95,51.39
P14.9  (via drill 0.2)
  Top 0.12: U300.L5 56.95,49.23 v56.95,50.91
  Route3 0.12: v71.51,50.99 60.07,50.99 59.35,51.71 57.75,51.71 v56.95,50.91
  Route14 0.12: v56.95,50.91 57.43,51.39 57.43,69.23 58.71,70.51 62.39,70.51 v62.55,70.67 | v66.07,16.35 66.47,16.35 66.95,16.83 66.95,17.39 74.23,24.67 74.23,29.15 71.51,31.87 v71.51,50.99
  Bottom 0.12: v62.55,70.67 62.55,71.47 62.71,71.63 62.71,79.15 61.91,80.19 62.39,81.87 X201.49 | v66.07,16.35 66.47,15.95 66.47,14.67 69.11,12.03 70.95,12.03 71.99,10.99 X202.49
P14.12  (via drill 0.2)
  Top 0.12: v60.15,47.63 U300.J1
  Route14 0.12: v63.11,19.63 63.11,20.75 62.31,21.55 62.31,33.23 68.39,39.31 68.39,44.83 68.55,44.99 68.55,46.83 68.87,47.15 68.87,47.87 v68.47,48.27
  Bottom 0.12: v63.11,19.63 62.15,18.67 62.15,15.31 65.91,11.55 69.19,11.55 70.87,9.87 70.87,9.84 X202.53 | v68.47,48.27 67.59,47.39 | v60.15,47.63 60.63,47.15 65.19,47.15 65.43,47.39 67.59,47.39 | 67.59,47.39
P14.13  (via drill 0.2)
  Top 0.127: v57.75,46.83 U300.H4
  Route14 0.12: v11.11,29.95 11.67,29.95 12.63,30.91 19.51,30.91 25.35,36.75 v25.35,37.07
  Bottom 0.12: v11.11,29.95 11.11,30.67 10.31,31.47 9.11,31.47 7.67,31.07 X200.39 | v25.35,37.07 27.59,37.07 28.31,37.79 32.15,37.79 32.31,37.63 41.35,37.63 42.23,38.51 48.55,38.51 49.19,37.87 63.43,37.87 64.31,38.75 64.31,41.79 62.15,43.95 61.35,43.95 58.87,46.43 58.15,46.43 v57.75,46.83 | v57.75,46.83
P14.14  (via drill 0.2)
  Top 0.12: v63.19,78.75 63.75,79.31 63.75,80.99 63.83,81.07 | 63.83,81.07 64.07,82.19 | X201.54 63.99,81.47 63.83,81.07
  Top 0.127: U300.H3 v58.55,46.83
  Route3 0.12: v58.55,46.83 65.11,46.83 65.51,47.23 67.91,47.23 68.07,47.07 v69.75,47.07
  Route14 0.12: v69.75,47.07 69.59,47.23 69.59,48.99 68.95,49.63 68.95,72.19 | 68.95,72.19 63.19,77.95 v63.19,78.75 | 68.95,72.19
P14.15  (via drill 0.2)
  Top 0.12: U300.H2 59.35,46.83 61.51,46.83 v62.71,45.63 | v62.71,68.11 62.71,69.95 63.43,70.67 63.43,78.19 63.99,78.91 64.71,81.23 X201.56
  Route14 0.12: v62.71,45.63 62.71,46.83 62.95,47.07 62.95,52.27 63.11,52.43 63.11,53.15 62.71,53.55 v62.71,68.11
P15.2  (via drill 0.2, 0.2 pad 0.55)
  Top 0.12: X203.4 14.29,58.37 15.11,57.55 15.35,57.31 v15.35,55.47 14.55,54.67 14.55,54.59 R204.1 | U300.H1 61.27,46.43 v62.07,45.63
  Route14 0.12: v62.71,52.75 62.71,47.23 62.07,46.59 v62.07,45.63
  Bottom 0.12: v62.71,52.75 62.47,52.99 52.55,52.99 50.63,51.07 31.43,51.07 30.15,49.79 23.59,49.79 17.91,55.47 v15.35,55.47
P15.3  (via drill 0.2)
  Top 0.12: U300.G2 59.35,46.03 61.03,46.03 v61.43,45.63 | v61.91,20.19 61.91,15.15 65.83,11.23 68.39,11.23 X202.56
  Route14 0.12: v67.67,45.55 67.67,39.79 61.59,33.71 61.59,21.07 61.91,20.75 v61.91,20.19
  Bottom 0.12: v67.67,45.55 67.35,45.23 61.75,45.23 v61.43,45.63
P15.4  (via drill 0.2)
  Top 0.127: U300.G4 v57.75,46.03
  Route3 0.12: v57.75,46.03 58.15,46.43 61.83,46.43 61.99,46.27 68.79,46.27 v68.95,46.43 | v53.35,70.75 53.51,70.91 61.51,70.91 63.67,73.07 67.03,73.07 v67.19,72.91
  Route14 0.12: 68.47,71.63 v67.19,72.91 | v68.95,46.43 69.11,46.59 69.11,48.27 68.47,48.91 68.47,71.63 | 68.47,71.63 | 68.47,71.63
  Bottom 0.12: X201.39 55.43,83.71 55.03,82.27 53.51,80.75 53.35,80.59 v53.35,70.75
P15.5  (via drill 0.2, 0.2 pad 0.55)
  Top 0.12: v58.55,46.03 | v58.55,46.03 U300.G3
  Route3 0.12: v58.55,46.03 v72.15,46.03
  Route14 0.12: v72.15,46.03 72.31,45.87 72.31,43.79 72.71,43.39 72.71,41.79 74.55,39.95 74.55,35.23 76.63,33.15 76.63,25.71 v75.03,24.11
  Bottom 0.12: 75.03,23.15 v75.03,24.11 | X202.39 77.13,16.11 77.11,16.11 75.99,17.23 75.99,17.79 74.55,19.23 74.55,22.67 75.03,23.15 | 75.03,23.15 | 75.03,23.15
P15.6  (via drill 0.2)
  Top 0.12: 65.99,79.95 66.15,80.35 66.23,80.83 | v64.55,71.55 63.91,72.19 63.91,77.71 65.67,79.47 66.23,80.83 | 66.23,80.83 X201.60
  Top 0.127: U300.G5 v56.95,46.03
  Route14 0.12: v56.95,46.03 56.55,46.43 56.55,51.87 56.95,52.27 56.95,69.55 58.39,70.99 61.83,70.99 62.39,71.55 v64.55,71.55
P15.7  (via drill 0.2)
  Top 0.12: v64.55,72.19 64.15,72.59 64.15,76.83 66.55,79.23 67.03,80.67 X201.62
  Top 0.127: U300.G6 v56.15,46.03
  Route14 0.12: v56.15,46.03 55.75,46.43 55.75,51.43 56.71,52.39 56.71,69.71 58.23,71.23 61.67,71.23 62.39,71.95 64.31,71.95 v64.55,72.19
P15.8  (via drill 0.2)
  Top 0.12: U300.M6 55.75,50.27 55.19,50.83 55.19,53.67 54.03,54.83 v53.11,54.83 | X200.22 10.95,24.59 11.43,24.59 v11.91,25.07
  Route3 0.12: v53.11,54.83 52.71,54.43 50.55,54.43 48.87,52.75 32.07,52.75 28.79,49.47 28.79,46.91 29.83,45.87 29.83,44.87 29.11,44.15 29.11,39.95 | 29.11,39.95 28.31,39.15 v28.31,38.91 | 29.11,39.95 | 29.11,39.95
  Route14 0.12: v28.31,38.91 27.75,38.91 27.51,38.67 27.51,32.71 19.31,24.51 12.47,24.51 v11.91,25.07
P15.9  (via drill 0.2)
  Top 0.12: U300.L6 56.15,49.23 56.15,50.23 55.43,50.95 55.43,53.79 v53.99,55.23 | X200.18 11.35,22.99 11.99,22.99 v12.23,22.75
  Route3 0.12: v53.99,55.23 52.87,55.23 52.31,54.67 50.39,54.67 48.71,52.99 31.95,52.99 28.55,49.59 28.55,46.79 29.59,45.75 29.59,44.99 28.87,44.27 28.87,40.11 27.91,39.15 v27.91,38.43
  Route14 0.12: v27.91,38.43 27.91,32.75 19.43,24.27 16.51,24.27 14.99,22.75 v12.23,22.75
P15.12  (via drill 0.2, 0.2 pad 0.55)
  Top 0.12: v56.95,48.43 U300.K5
  Route3 0.12: v67.35,48.83 57.35,48.83 v56.95,48.43
  Route14 0.12: v68.07,10.42 61.35,17.15 61.35,33.87 66.71,39.23 66.71,45.79 67.35,46.43 v67.35,48.83 | v67.35,48.83 | v67.35,48.83
  Bottom 0.12: v68.07,10.42 v68.07,10.43 X202.57
P15.13  (via drill 0.2)
  Top 0.12: v57.35,50.35 U300.M4
  Route3 0.12: v57.35,50.35 59.67,50.35 60.07,50.75 67.67,50.75 v68.07,50.35
  Route14 0.12: v62.31,19.63 62.31,20.75 61.83,21.23 61.83,33.55 67.91,39.63 67.91,45.15 68.07,45.31 v68.07,50.35
  Bottom 0.12: v62.31,19.63 61.91,19.23 61.91,15.15 65.83,11.23 68.39,11.23 70.31,9.31 70.31,9.28 X202.55
P15.14  (via drill 0.2)
  Top 0.12: U300.L4 57.75,49.23 57.75,50.83 v57.67,50.91
  Route14 0.12: v63.91,70.83 63.67,70.59 63.11,70.59 62.79,70.27 58.87,70.27 57.67,69.07 v57.67,50.91
  Bottom 0.12: 65.99,79.95 66.15,80.35 66.23,80.83 | v63.91,70.83 63.91,77.71 65.67,79.47 66.23,80.83 | 66.23,80.83 X201.59
P15.15  (via drill 0.2)
  Top 0.127: U300.K4 v57.75,48.43
  Route14 0.12: v57.75,48.43 58.07,48.75 58.07,51.23 57.91,51.39 57.91,68.91 59.03,70.03 62.95,70.03 63.11,70.19 v64.15,70.19
  Bottom 0.12: v64.15,70.19 64.31,70.35 64.31,71.07 64.15,71.23 64.15,76.83 66.55,79.23 67.03,80.67 X201.61
RESET#  (via drill 0.2)
  Top 0.12: X202.42 76.57,15.47 76.55,15.47 75.59,16.43 v75.59,20.11 75.59,20.35 70.39,25.55 v70.07,25.55 | X200.42 8.95,32.11 10.95,32.11 12.23,30.83 v12.23,29.87 | v38.47,30.11 37.13,28.77 V405.2 39.05,27.29 v40.23,26.11 | U300.G11 v52.15,45.23 | X201.42 55.67,82.11 54.07,80.51 v54.07,78.27 | 75.25,50.03 SW400.P | v75.99,50.03 75.25,50.03 | 71.22,55.71 71.19,55.71 71.19,54.09 75.25,50.03 | U500.47 36.63,72.94 36.31,73.26 36.31,73.87 35.99,74.19 v35.99,74.75 | v48.63,7.87 V404.2 | v35.99,74.75
  Top 0.2: R422.1 71.22,55.71 70.15,55.71 69.59,56.27 68.62,56.27 SW400.P1 67.22,56.02 R419.1 C415.1
  Route3 0.12: v38.47,30.11 38.07,30.11 37.91,29.95 35.35,29.95 34.95,30.35 33.59,30.35 32.87,29.63 15.91,29.63 15.67,29.87 v12.23,29.87 | v40.23,26.11 40.47,26.35 48.95,26.35 49.27,26.03 51.19,26.03 51.51,26.35 v51.99,26.35 52.47,26.35 52.55,26.27 63.59,26.27 65.43,28.11 68.55,28.11 68.79,27.87 68.79,27.47 70.07,26.19 v70.07,25.55 | v42.95,81.63 46.63,77.95 53.75,77.95 v54.07,78.27
  Route14 0.12: v54.07,78.27 53.59,77.79 53.59,74.51 49.11,70.03 49.11,66.27 42.55,59.71 42.55,50.03 v42.79,49.79 42.55,49.55 42.55,47.31 43.67,46.19 43.67,45.07 43.11,44.51 43.11,42.59 40.47,39.95 40.47,38.11 39.91,37.55 39.91,31.71 40.47,31.15 40.47,26.35 v40.23,26.11 | v48.63,7.87 50.07,9.31 50.07,23.79 51.99,25.71 v51.99,26.35 | v75.99,50.03 75.99,49.47 77.19,48.27 77.19,36.99 79.67,34.51 79.67,28.67 78.79,27.79 78.79,21.07 78.23,20.51 75.99,20.51 v75.59,20.11 | v75.59,20.11 | v75.59,20.11
  Bottom 0.12: v52.15,45.23 50.95,46.43 43.43,46.43 42.55,47.31 42.55,49.55 v42.79,49.79 | v35.99,74.75 | v35.99,74.75 35.99,75.15 42.47,81.63 v42.95,81.63
TCK  (via drill 0.2)
  Top 0.12: v53.75,46.03 U300.G8 | v53.75,46.03 | v52.31,7.23 R403.2 | U500.22 45.27,69.95 v45.27,69.71 | U500.39 39.43,75.79 39.43,76.51 39.59,76.67 | 39.59,76.67 | v39.59,77.07 39.59,76.67
  Top 0.2: SW300.3 v22.87,20.03
  Route3 0.12: v22.87,20.03 23.19,20.35 37.35,20.35 38.71,18.99 44.87,18.99 52.31,11.55 v52.31,7.23 | v45.27,69.71 39.59,75.39 v39.59,77.07 | v39.59,77.07
  Route14 0.12: v53.75,46.03 | v53.75,46.03 U300.G8 54.15,28.11 55.11,27.15 55.11,10.03 v52.31,7.23 | v25.11,31.39 27.03,33.31 27.03,38.99 27.59,39.55 29.83,39.55 30.63,40.35 30.63,47.07 30.15,47.55 30.15,54.83 34.15,58.83 35.59,58.83 45.27,68.51 v45.27,69.71
  Bottom 0.12: v22.87,20.03 22.87,26.27 25.11,28.51 v25.11,31.39
TMS  (via drill 0.2)
  Top 0.12: v54.55,46.03 U300.G7 | v54.55,46.03 | v53.51,6.91 R402.2 | U500.35 42.31,76.26 v42.31,76.83 42.17,76.83 U500.36
  Top 0.2: v20.39,20.59 SW300.4
  Route3 0.12: v20.39,20.59 37.51,20.59 38.87,19.23 45.03,19.23 53.51,10.75 v53.51,6.91 | v46.63,70.83 42.31,75.15 v42.31,76.83
  Route14 0.12: v54.55,46.03 55.19,45.39 55.19,28.43 55.35,28.27 55.35,9.87 53.51,8.03 v53.51,6.91 | v24.47,31.63 26.79,33.95 26.79,39.15 27.43,39.79 29.67,39.79 30.39,40.51 30.39,46.91 29.91,47.39 29.91,54.99 33.99,59.07 35.43,59.07 44.79,68.43 44.79,69.87 45.75,70.83 v46.63,70.83
  Bottom 0.12: v20.39,20.59 22.63,22.83 22.63,26.43 24.87,28.67 24.87,30.03 24.47,30.43 v24.47,31.63
VAREF  (via drill 0.2 pad 0.55)
  Top 0.12: X202.48 72.63,11.47 71.64,12.51
  Top 0.2: 71.64,12.51 69.51,12.51 66.87,15.15 66.87,20.51 v59.19,28.19 | v61.99,68.11 61.99,71.47 62.39,71.87 62.39,78.99 61.35,80.03 61.35,80.67 X201.48 | U300.M3 58.15,51.71 58.25,51.81 C311.1 58.23,52.51 58.23,53.66 L301.1 58.15,53.79 59.75,53.79 v62.23,56.27
  Route14 0.2: v59.19,28.19 58.95,28.43 58.95,31.15 60.47,32.67 60.47,33.95 61.35,34.83 61.35,39.15 60.39,40.11 60.39,44.43 60.99,45.03 60.99,46.15 62.23,47.39 v62.23,56.27 62.23,67.87 v61.99,68.11
VBAT  (via drill 0.2)
  Top 0.12: v60.55,45.63 U300.G1
  Top 0.2: C414.+ 58.4,23 59.83,24.43 59.85,24.43 V406.3 59.85,24.49 v58.95,25.39 | v58.95,25.39
  Route14 0.16: v58.95,25.39 58.63,25.71 58.63,31.39 60.15,32.91 60.15,34.19 61.03,35.07 61.03,38.91 59.99,39.95 59.99,45.07 v60.55,45.63
VDD3.3  (via drill 0.2 pad 0.55)
  Top 0.12: U302.8 18.87,27.55 R303.2 | v38.15,23.87 | 38.15,23.79 v38.15,23.87
  Top 0.16: U430.C7 34.31,43.63 34.63,43.95 34.63,44.91 34.31,45.23 | v32.15,41.15 U430.A9 | v32.15,41.15 | C430.1 v32.15,41.15 | 34.31,45.23 U430.E7 | 34.31,45.23 34.63,45.55 v34.63,49.39 32.47,49.39 31.94,49.39 31.57,49.01 | v32.15,41.15 | v32.15,41.15 33.67,41.15 33.91,41.39 33.91,41.87 U430.A7 | 36.07,44.11 | 36.07,44.11 36.07,43.15 36.39,42.83 | 36.39,42.83 36.07,42.51 v36.07,41.07 | 36.87,44.43 36.39,44.43 36.07,44.11 | 36.63,42.83 U430.B3 | 36.39,42.83 36.63,42.83 | 36.63,42.83 36.39,42.83 | 36.63,42.83 | 36.87,44.43 U430.D3 | 36.87,44.43 | U430.J9 | U430.J9 | 31.57,49.01 C433.1 | 31.57,49.01 U430.J9 | 31.57,49.01 | 31.57,49.01
  Top 0.2: TP405.1 75.45,69.37 75.45,69.38 R407.2 | v36.07,41.07 | v36.07,41.07 C432.1 C435.1 | C406.2 v22.15,50.55 23.52,51.91 R301.2 | R207.2 R205.2 21.43,59.33 21.43,58.67 v21.99,58.11 | 34.51,69.47 C510.1 | R504.1 30.13,68.59 | 30.13,68.59 33.64,68.59 | U500.28 44.79,73.79 45.19,73.79 v46.87,72.11 | v46.87,72.11 46.31,72.67 v46.87,72.11 | v30.31,31.23 29.83,29.63 R310.2 | U306.5 43.35,19.75 43.35,19.39 C322.1 v44.31,19.79 | U301.5 41.27,17.64 41.27,17.31 C310.1 41.55,16.99 41.59,16.99 41.99,16.59 v42.95,16.59 | v44.31,19.79 | v44.31,19.79 | v56.39,16.83 | v56.39,16.83 X400.1 | C509.1 47.39,71.59 v46.87,72.11 | C318.1 51.57,65.71 51.57,65.35 U303.5 | U304.5 53.55,68.13 C319.1 53.27,68.42 52.62,68.42 50.95,66.75 | v43.03,31.23 | v43.03,31.23 | R427.1 v43.03,31.23 | R204.2 v13.35,53.39 | v46.87,72.11 | v46.87,72.11 | R305.2 37.27,66.99 37.27,66.83 v36.47,66.03 | R400.2 55.51,18.27 | 55.51,18.27 56.39,17.39 v56.39,16.83 | R408.2 38.15,21.51 38.15,23.79 v38.15,23.87 | U501.5 56.87,70.91 56.87,70.99 | C511.1 58.4,71.87 57.83,71.87 | 56.87,70.99 R503.2 | 56.87,70.99 v57.75,71.87 57.83,71.87 | 44.23,68.43 v44.15,68.43 | 50.95,66.75 | 50.95,66.75 50.95,66.32 51.32,65.95 51.35,65.95 C318.1 | v50.47,65.23 51.17,65.93 C318.1 | 57.83,71.87 v57.75,71.87 | 30.13,68.59 30.15,68.59 30.15,66.87 R430.2 | v27.53,45.17 27.55,45.15 28.31,45.15 | 29.11,45.15 | 29.11,45.15 28.31,45.15 | v28.32,44.38 v28.31,44.39 28.31,45.15 | 28.31,45.15 v28.32,45.17 | v28.32,45.96 v28.31,45.96 28.31,45.15 | v67.27,53.63 | v67.27,53.63 | R419.2 v67.27,53.63 | v72.87,60.11 | v72.87,60.11 | Q404.2 74.08,58.9 v72.87,60.11 | v31.43,54.27 v31.43,54.28 R429.2 | V406.1 60.57,22.35 58.71,22.35 55.51,19.15 55.51,18.27
  Top 0.2: R307.2 68.63,40.7 68.63,40.67 67.49,39.53 R306.2 67.19,39.79 v67.19,40.75 | v34.63,49.39 | v34.63,49.39 | v34.63,49.39 35.75,49.39 36.23,49.87 36.23,50.43 C431.1 36.23,50.59 36.23,51.15 36.71,51.63 C436.1 | C430.1 C434.1 | C430.1 | C508.1 38.91,77.67 38.39,77.15 v38.39,76.51 | v38.39,76.51 | v38.39,76.51
  Top 0.22: v29.11,45.17 29.11,45.15 29.11,45.29 R431.2
  Top 0.3: 34.51,69.47 33.64,68.59 33.64,68.15 v33.91,67.87 | U500.5 37.48,69.31 36.62,69.31 C507.1 35.12,69.71 34.71,69.71 C510.1 | U500.10 39.26,67.55 37.92,67.55 R305.2 | U500.18 43.97,68.43 v44.15,68.43 44.23,68.43 44.31,68.43 C502.1 | v17.52,25.41 17.52,25.88 17.99,26.35 18.07,26.4 C321.1 18.39,27.55 U302.8 | X401.C1 29.51,21.23 29.43,21.39 v29.43,24.27 | v27.03,13.95 R304.2 | X401.D1 33.91,12.43 34.47,12.43 34.79,12.75 34.79,12.71 R401.2 36.11,12.71 36.47,13.07 | 36.47,13.07 | 36.47,13.07 v36.47,13.15 | v29.43,24.27 | v29.43,24.27 | R309.2 28.86,24.84 v29.43,24.27 | U500.41 38.39,75.42 v38.39,76.51 | v38.39,76.51
  Top 0.5: C407.1 27.75,42.12 | C413.1 C407.1 | v29.11,45.17 29.11,43.48 27.78,42.15 C407.1 | v27.53,45.17 26.88,45.82 U401.1 26.17,45.85 R416.2
  Bottom 0.2: v22.15,50.55 18.03,54.67 17.59,54.67 14.87,51.95 14.47,51.95 13.35,53.07 v13.35,53.39 | v57.75,71.87 | v33.91,67.87 33.91,69.95 38.39,74.43 38.39,74.51 | v59.75,64.51 57.75,66.51 v57.75,71.87 | v67.27,53.63 72.87,59.23 v72.87,60.11 | v72.87,60.11 | v72.87,60.11 | v38.39,76.51 | 38.39,74.51 v38.39,76.51 | 38.39,74.51
  Bottom 0.8: TP405.1 71.15,63.71 v59.75,63.71 | v59.75,63.71 | v59.75,62.91 v59.75,63.71 | v59.75,64.51 v59.75,63.71
  pour Route2 (rank 3): 64.34,0.58 74.95,11.19 71.76,14.37 arc-94 71.83,16.28 arc-53 73.81,16.28 76.93,13.17 89.8,26.04 85.84,30 88.38,32.54 77.21,74.12 73.81,74.97 75.3,80.41 60.73,84.23 59.67,80.2 arc-101 57.55,79.21 arc-87 56.92,80.84 58.05,85.08 40.37,89.75 38.96,84.37 35.56,85.22 5.16,54.82 6.07,51.35 0.56,49.94 4.52,35.37 8.83,36.57 arc-90 10.46,35.65 arc-94 9.33,33.82 5.23,32.68 9.96,15.08 15.34,16.63 16.26,13.17 57.91,2.07 60.38,4.54
  pour Top: 30.87,44.55 27.58,41.27 24.3,44.55 27.58,47.83
VDD5  (via drill 0.2, 0.2 pad 0.55)
  Top 0.2: TP406.1 76.96,66.47 75.98,67 R405.2 | v8.35,37.31 8.23,37.07 X200.46 | 8.32,37.12 8.31,37.15 X200.46 | 60.24,80.37 60.31,80.35 X201.46 | 56.34,81.25 56.39,81.23 X201.44
  Top 0.4: C204.1 12.37,34.2 X200.44 | 11.38,38.04 11.41,37.99 8.32,37.12 X200.46 | X202.46 70.35,14.93 70.35,15.36 69.9,15.81 | 69.9,15.81 C210.1 | 72.56,18.59 72.57,18.57 72.54,18.54 | 74.33,16.61 72.56,18.38 72.56,18.59 | 74.33,16.61 X202.44 | 69.9,15.81 69.84,15.87 72.56,18.59 | 74.33,16.61 74.38,16.65 74.37,16.66 74.37,16.78 72.56,18.59 | 55.31,77.94 55.36,77.98 56.34,81.25 X201.44 | C205.1 59.21,76.96 60.24,80.37 X201.46
  Top 0.5: C405.1 25.21,39.52 24.47,39.52 v23.96,40.02 | v23.17,40.82 23.17,41.01 U401.8 22.27,41.95 21.36,41.04 R415.2
  Top 0.8: V501.C 40.71,80.75 40.15,81.31 v39.67,81.31 | U200.5 27.27,58.88 27.27,57.31 24.71,54.75 22.96,54.75 C213.+
  Top 1: V408.C 17.74,53.6 | 17.74,53.6 V200.C | C213.+ 17.87,53.73 17.74,53.6
  Bottom 0.2: v8.35,37.31 8.23,37.07 X200.46
  Bottom 0.4: X200.44 12.37,34.2 | X200.46 10.86,37.83 | 71.56,13.72 X202.46 | 71.56,13.72 71.2,13.72 | 74.33,16.61 75.95,14.99 | 71.56,13.72 70.29,14.99 70.29,15.42 69.9,15.81 | X201.46 60.11,79.57 60.11,79.11 58.41,77.42 56.04,79.79 56.04,80.58 56.26,80.92 | 56.32,81.09 X201.44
